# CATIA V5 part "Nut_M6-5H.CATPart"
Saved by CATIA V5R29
Part number: Nut_M6-5H
Source: Unknown
Bounding box of the stored display mesh (mm): x -5 to 5, y -5.774 to 5.774, z -2.5 to 2.5
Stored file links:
  C:\가치같이\SmartFactory_BoxErectorConveyor\Boxing(under)\Nut_M6-5H.CATPart
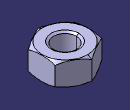
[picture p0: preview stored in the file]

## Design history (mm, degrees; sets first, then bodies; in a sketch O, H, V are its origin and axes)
Body1 (main body)
  Solid1 "PartBody": solid without history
